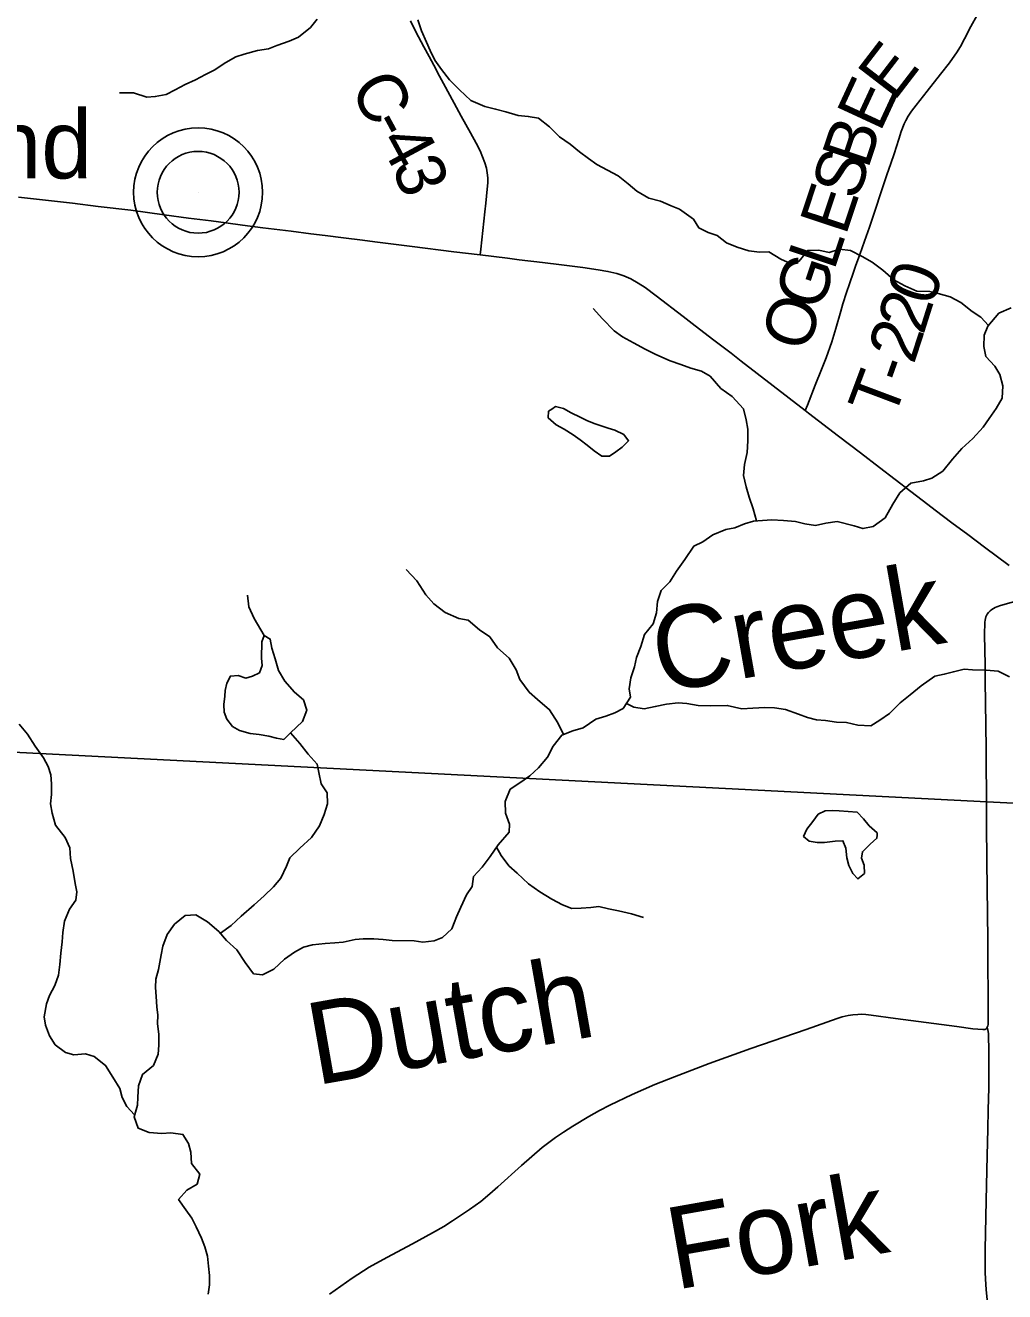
# Model space of a CAD drawing. Extents: x 1442749 to 1756758, y 235267 to 677782.
# Drawn here: x 1568709 to 1574676, y 536473 to 544190 of the extents above; entities that cross this region are included whole.
import ezdxf

# ---------------------------------------------------------------- set-up
doc = ezdxf.new("R2010")
doc.units = 0
for name, color, linetype in [('GM_X_County_Road', 7, 'Continuous'), ('GM_X_County_Road_Text', 7, 'Continuous'), ('GM_X_Major_River_Text', 7, 'Continuous'), ('GM_X_Minor_Lake', 7, 'Continuous'), ('GM_X_Minor_River', 7, 'Continuous'), ('GM_X_Minor_River_Text', 7, 'Continuous'), ('GM_X_State_Route', 7, 'Continuous'), ('GM_X_Township', 7, 'Continuous'), ('GM_X_Township_Road', 7, 'Continuous'), ('GM_X_Township_Road_Text', 7, 'Continuous'), ('GM_X_Unincorporated', 7, 'Continuous'), ('GM_X_Unincorporated_Location', 7, 'Continuous'), ('GM_X_Unincorporated_Text', 7, 'Continuous')]:
    doc.layers.add(name, color=color, linetype=linetype)

msp = doc.modelspace()

# ---------------------------------------------------------------- linework, layer by layer
at = {"layer": 'GM_X_County_Road'}
for points in [[(1571480.2, 542791.2), (1571483.9, 542826), (1571508.2, 543054.3), (1571514.2, 543106.5), (1571523.9, 543191.3), (1571526.7, 543230.9), (1571526.3, 543260.8), (1571523.6, 543290.6), (1571518.3, 543320.1), (1571509.3, 543352.1), (1571495.6, 543389.4), (1571479.6, 543425.6), (1571455.9, 543472.7), (1571421.1, 543535.8), (1571365.7, 543635.8), (1571335.5, 543690.2), (1571268.3, 543814.1), (1571233, 543880.8), (1571197.4, 543947.3), (1571169.3, 543999.3), (1571136.5, 544059.9), (1571089.2, 544149.8), (1571056.1, 544217.4)], [(1574565.9, 539401), (1574562.6, 539789.4), (1574561.3, 539916.8), (1574559.2, 540070.2), (1574557.6, 540184.8), (1574556.2, 540293), (1574553.5, 540476.5), (1574555.5, 540552.4), (1574557.3, 540565.8), (1574559.3, 540575.6), (1574561.7, 540586.3), (1574569, 540601.4), (1574576.8, 540612.2), (1574587.6, 540622.4), (1574597.8, 540630.3), (1574608.1, 540637.1), (1574617.4, 540642), (1574627.6, 540646.9), (1574651.5, 540654.2), (1574845.2, 540708.9), (1574867.7, 540715.4), (1574924.4, 540732.1)], [(1574570, 538084.6), (1574574, 538093.6), (1574575.4, 538101.5), (1574576.1, 538108.5), (1574575.4, 538292), (1574574.2, 538459.3), (1574572.8, 538619.7), (1574570.5, 538776.3), (1574567.7, 539094.1), (1574565.6, 539324.1), (1574565.9, 539401)], [(1570562.9, 536458.8), (1570700.8, 536555.8), (1570805, 536622.4), (1570910.9, 536682), (1571067.9, 536764.1), (1571191, 536832.3), (1571258.1, 536870.9), (1571312.8, 536905.6), (1571415.2, 536973.3), (1571484.5, 537022.8), (1571539.4, 537068.8), (1571588.1, 537112.9), (1571731.9, 537242.5), (1571858.4, 537352.2), (1571897.9, 537382.2), (1571939.9, 537413.5), (1571989, 537444.7), (1572044.8, 537481.3), (1572143.2, 537540.6), (1572207.8, 537576.6), (1572271.1, 537609.6), (1572407.4, 537673.9), (1572544.8, 537735.5), (1572663.7, 537783), (1572875.3, 537863.4), (1573128.5, 537954.4), (1573466.6, 538070.5), (1573655.3, 538137.6), (1573686.9, 538147.8), (1573722.4, 538155.3), (1573751.2, 538160), (1573780.7, 538162.6), (1573805, 538163.4), (1573830.2, 538161.7), (1573861.6, 538158.4), (1574010.4, 538138.8), (1574384.3, 538088.3), (1574481.6, 538075.6), (1574543.1, 538071.2), (1574554.9, 538071.7), (1574560.7, 538073.6), (1574565.6, 538077.5), (1574570, 538084.6)]]:
    msp.add_lwpolyline(points, dxfattribs=at)
at = {"layer": 'GM_X_Minor_Lake'}
for points in [[(1571916.3, 541852), (1571896.2, 541838.2), (1571895.4, 541798.1), (1571942.5, 541755.2), (1571992, 541730.1), (1572047.3, 541695), (1572088.7, 541664.1), (1572132, 541631.2), (1572175.3, 541596.3), (1572222.7, 541565.3), (1572268.7, 541564.4), (1572307.2, 541591.7)], [(1572307.2, 541591.7), (1572345.8, 541619), (1572384.6, 541658.3), (1572355.4, 541696.9), (1572300, 541724), (1572260.2, 541734.8), (1572218.5, 541749.7), (1572174.8, 541764.6), (1572131.1, 541781.5), (1572089.5, 541802.3), (1572034.1, 541829.4), (1571988.6, 541854.4), (1571938.8, 541867.4), (1571916.3, 541852)], [(1570163.9, 540472.3), (1570151.1, 540432.5), (1570149.1, 540334.4), (1570152.2, 540288.3), (1570135.3, 540244.5), (1570092.8, 540223.4), (1570052.6, 540212.1), (1570006.9, 540227.1), (1569958.8, 540224), (1569937.9, 540180.4), (1569927, 540136.5), (1569924.3, 540102.5), (1569919.2, 540050.5), (1569920.3, 540004.4), (1569937.4, 539962), (1569972.5, 539917.3), (1570014, 539892.4), (1570079.7, 539875.1), (1570133.5, 539868), (1570193.4, 539858.8), (1570239.1, 539845.9), (1570285, 539839), (1570325.8, 539878.2)], [(1570325.8, 539878.2), (1570397.2, 539946.9), (1570424.6, 540016.5), (1570403.9, 540079), (1570348.9, 540126.2), (1570290.2, 540193.4), (1570251.6, 540258.3), (1570231, 540328.8), (1570210.4, 540395.3), (1570201.5, 540449.6), (1570163.9, 540472.3)], [(1573898.7, 539255.2), (1573899.8, 539268.7), (1573850.7, 539311.7), (1573815.6, 539354.5), (1573776.4, 539395.3), (1573722.5, 539398.4), (1573668.5, 539403.5), (1573624.6, 539406.3), (1573582.5, 539403.2), (1573540.1, 539384), (1573507.2, 539338.5)], [(1573507.2, 539338.5), (1573470.2, 539291.2), (1573451.3, 539247.5), (1573484.7, 539218.8), (1573534.6, 539209.8), (1573578.6, 539210.9), (1573642.7, 539217.7), (1573690.8, 539220.8), (1573707.9, 539176.3), (1573714.7, 539116.1), (1573725.7, 539069.8), (1573750.7, 539021.2), (1573782.1, 538988.6), (1573822.7, 539021.8), (1573819.8, 539072), (1573804.6, 539114.3), (1573809.5, 539154.3), (1573856.4, 539199.4), (1573897.2, 539236.7), (1573898.7, 539255.2)]]:
    msp.add_lwpolyline(points, dxfattribs=at)
at = {"layer": 'GM_X_Minor_River'}
for points in [[(1570487, 544227.7), (1570446, 544176.4), (1570372.8, 544117.8), (1570316.2, 544092.8), (1570241.7, 544066.3), (1570191.3, 544047.2), (1570123.1, 544036.6), (1570042.6, 544014.1), (1569992.3, 543999.1), (1569931.5, 543964.2), (1569860.6, 543917.6), (1569808, 543890.6), (1569745.3, 543857.8), (1569682.7, 543828.9), (1569622.1, 543798.1), (1569567.5, 543769.1), (1569501.2, 543756.4), (1569449.1, 543751.4), (1569367.7, 543779.1), (1569283.6, 543778.8)], [(1574576.7, 542360.2), (1574530.4, 542411), (1574477.1, 542446.1), (1574408.2, 542501.6), (1574342.9, 542534.9), (1574271.3, 542556.4), (1574219.5, 542567.4), (1574141.6, 542571), (1574068.2, 542602.4), (1574001, 542639.8), (1573934.2, 542697.2), (1573869.2, 542746.6), (1573807.9, 542781.9), (1573736.6, 542817.3), (1573668.8, 542826.7), (1573606.3, 542805.9), (1573544.6, 542819.1), (1573476.6, 542818.5), (1573421.2, 542751.5), (1573370.9, 542738.4), (1573311.5, 542765.7), (1573238.4, 542809.2), (1573182.3, 542808.3), (1573116.5, 542815.6), (1573046.9, 542839), (1572981.4, 542864.3), (1572924.4, 542909.5), (1572868.7, 542928.6), (1572813.3, 542955.8), (1572780.4, 543008.5), (1572695.6, 543070.3), (1572644, 543089.3), (1572578.6, 543118.7), (1572509, 543136.1), (1572435.8, 543179.6), (1572382.8, 543224.7), (1572321.7, 543274), (1572191.1, 543342.7), (1572139.8, 543377.7), (1572084.7, 543418.9), (1572029.6, 543466), (1571964.6, 543511.4), (1571903.8, 543570.7), (1571834.9, 543624.1), (1571773.1, 543635.4), (1571711.2, 543640.6), (1571637.6, 543662.1), (1571574, 543679.4), (1571508.3, 543694.7), (1571423, 543732.4), (1571354.3, 543797.9), (1571293.6, 543857.2), (1571244.8, 543920.2), (1571204, 543977.1), (1571175.2, 544035.8), (1571154.3, 544088.3), (1571123.7, 544157), (1571101, 544223.5)], [(1570890, 538619.1), (1570943.9, 538614.1), (1571077.9, 538611.4), (1571131.7, 538602.3), (1571199.9, 538611), (1571250.4, 538632), (1571307.5, 538685), (1571336.9, 538756.5), (1571362.1, 538816.1), (1571397.7, 538891.5), (1571430.8, 538943), (1571440, 539002.9), (1571493.2, 539059.9), (1571540.5, 539125.1), (1571590, 539196.2), (1571657.6, 539273), (1571658.6, 539323), (1571634, 539389.6), (1571633.4, 539459.8), (1571662.9, 539535.3), (1571727.8, 539578.1), (1571782.6, 539617), (1571835.7, 539666.1), (1571891, 539731.1), (1571924.4, 539796.5), (1571977.7, 539863.6), (1572044.3, 539890.3), (1572108.7, 539909), (1572185.8, 539961.6), (1572246.2, 539980.4), (1572300.6, 540001.4), (1572351.1, 540026.4), (1572396.6, 540095.6), (1572387.6, 540145.9), (1572399, 540213.8), (1572420.4, 540281.5), (1572433.5, 540337.3), (1572458.9, 540404.9), (1572482.4, 540478.5), (1572533.8, 540543.6), (1572555.1, 540609.3), (1572560.6, 540679.3), (1572583.9, 540746.9), (1572635, 540798), (1572676.4, 540863.3), (1572727.8, 540934.4), (1572781.5, 541015.4), (1572838, 541042.4), (1572898.9, 541085.2), (1572977.6, 541117.7), (1573031.8, 541128.7), (1573090.3, 541151.6), (1573146.7, 541168.5), (1573200.8, 541173.4), (1573256.9, 541176.3), (1573328.8, 541172.9), (1573400.7, 541167.4), (1573458.4, 541152.3), (1573524.2, 541143), (1573586.5, 541155.8), (1573654.7, 541166.4), (1573758.2, 541140.3), (1573811.9, 541123.3), (1573874.1, 541136), (1573947.2, 541188.7), (1573994.9, 541271.9), (1574036.4, 541341.2), (1574103.6, 541399.9), (1574181.9, 541414.4), (1574232.2, 541431.4), (1574299.1, 541474.2), (1574358.6, 541547.1), (1574416, 541612.1), (1574481.2, 541672.9), (1574544.6, 541741.7), (1574581.7, 541795.1), (1574625, 541854.3), (1574660.3, 541917.7), (1574663.8, 541993.8), (1574647.2, 542062.2), (1574616.3, 542112.9), (1574561.5, 542172), (1574548.7, 542232.4), (1574550.2, 542302.5), (1574573.3, 542356.1), (1574640.9, 542436.9), (1574715.6, 542469.5)], [(1573164.1, 541170), (1573144.2, 541244.6), (1573119.7, 541315.2), (1573101, 541377.7), (1573084.4, 541446.1), (1573091.8, 541514.1), (1573107.3, 541587.9), (1573110.7, 541657.9), (1573112.2, 541730), (1573101.3, 541786.3), (1573084.7, 541852.7), (1573016.2, 541928.2), (1572947.2, 541977.6), (1572880.8, 542053.1), (1572829.4, 542082.1), (1572763.8, 542101.5), (1572702.2, 542122.7), (1572638.7, 542146), (1572551.4, 542183.8), (1572486.1, 542217.1), (1572414.8, 542254.6), (1572347.6, 542292), (1572296.4, 542329), (1572225.9, 542402.5), (1572169.1, 542463.8)], [(1571987.7, 539867.6), (1571953.3, 539940.2), (1571902.9, 540019.3), (1571830.2, 540080.8), (1571779.1, 540125.9), (1571722.7, 540203.1), (1571699.9, 540261.7), (1571657.3, 540334.6), (1571586.6, 540396.1), (1571540, 540463.1), (1571476.8, 540506.4), (1571408.1, 540565.9), (1571350.2, 540575), (1571267, 540612.8), (1571198, 540664.2), (1571149.2, 540719.2), (1571094.9, 540804.4), (1571030.3, 540873.8)], [(1569897.8, 538656.9), (1569963.6, 538703.6), (1570024.8, 538760.5), (1570104.3, 538831), (1570165.4, 538885.9), (1570220.5, 538940.9), (1570265.6, 538992), (1570301.1, 539065.5), (1570320.2, 539117.2), (1570381.4, 539176), (1570452.7, 539240.7), (1570502.2, 539311.9), (1570529.6, 539381.4), (1570550.9, 539445.1), (1570548.3, 539513.3), (1570511.4, 539568.1), (1570496.8, 539636.5), (1570487.9, 539688.7), (1570433.1, 539747.9), (1570382.4, 539813), (1570325.8, 539878.2), (1570397.2, 539946.9), (1570424.6, 540016.5), (1570403.9, 540079), (1570348.9, 540126.2), (1570290.2, 540193.4), (1570251.6, 540258.3), (1570231, 540328.8), (1570210.4, 540395.3), (1570201.5, 540449.6), (1570163.9, 540472.3), (1570104, 540575.7), (1570071.5, 540646.4), (1570062.9, 540716.7)], [(1572371.5, 540057.5), (1572417.3, 540035.2), (1572479.1, 540025.9), (1572547.4, 540038.6), (1572615.7, 540053.3), (1572685.9, 540061.9), (1572739.8, 540056.8), (1572809.6, 540045.4), (1572883.6, 540043.9), (1572985.6, 540045.9), (1573075.2, 540024.1), (1573141.3, 540028.8), (1573215.4, 540033.4), (1573273.3, 540030.2), (1573341.2, 540020.9), (1573420.6, 539993.3), (1573474.2, 539972.2), (1573529.9, 539957), (1573583.8, 539954), (1573651.6, 539944.6), (1573711.6, 539941.4), (1573781.3, 539926), (1573861.2, 539920.4), (1573915.9, 539955.4), (1573974.8, 539996.3), (1574040.1, 540061.1), (1574101.1, 540110), (1574168.2, 540164.8), (1574251.5, 540223.2), (1574307.7, 540236.1), (1574364, 540251), (1574428.4, 540265.8), (1574480.3, 540262.7), (1574562.3, 540261.1), (1574636.1, 540253.7), (1574705.5, 540220.2)], [(1569375.4, 537551.6), (1569326.9, 537602.5), (1569300, 537657.1), (1569285.2, 537711.4), (1569242.6, 537780.4), (1569198, 537851.4), (1569129.1, 537906.8), (1569075.4, 537921.9), (1569005.3, 537917.3), (1568953.6, 537930.3), (1568890.6, 537977.7), (1568855.7, 538032.4), (1568833, 538097), (1568824, 538147.2), (1568837.7, 538227.1), (1568856.7, 538278.8), (1568889.9, 538338.2), (1568911.3, 538401.9), (1568920.6, 538467.8), (1568926, 538535.8), (1568933.4, 538605.8), (1568938.6, 538661.8), (1568948, 538731.7), (1568979.5, 538803.2), (1569016.6, 538858.5), (1569023.7, 538910.5), (1569012.7, 538960.8), (1569000.3, 539035.1), (1568983.9, 539113.6), (1568981.2, 539177.7), (1568952.5, 539240.4), (1568894, 539315.7), (1568873.5, 539388.2), (1568862.7, 539446.5), (1568869.8, 539502.4), (1568869.2, 539568.5), (1568864.3, 539622.7), (1568849.3, 539673.1), (1568820.4, 539725.7), (1568769.9, 539796.9), (1568723.3, 539869.9), (1568672.6, 539931)], [(1571580.5, 539182.5), (1571608.7, 539131.7), (1571655.4, 539068.7), (1571706.5, 539023.6), (1571775.1, 538958.2), (1571844.1, 538908.7), (1571917.2, 538865.2), (1571982.5, 538829.9), (1572038.1, 538808.8), (1572096.1, 538809.6), (1572154.2, 538814.5), (1572204.4, 538819.5), (1572262.1, 538806.3), (1572323.8, 538793.1), (1572401.5, 538775.5), (1572475.1, 538754)], [(1569823.5, 536456.9), (1569830.7, 536514.8), (1569831.9, 536570.9), (1569825.1, 536629.1), (1569818.3, 536689.3), (1569803.4, 536745.7), (1569782.5, 536798.2), (1569750, 536869), (1569723, 536921.6), (1569688.1, 536972.3), (1569643.4, 537035.3), (1569692.5, 537092.4), (1569757.3, 537129.2), (1569772.5, 537189), (1569721.9, 537254.1), (1569717.3, 537322.3), (1569704.4, 537376.7), (1569669.5, 537431.4), (1569595.7, 537440.9), (1569541.6, 537438), (1569463.7, 537443.5), (1569396.2, 537468.9), (1569371.7, 537539.5), (1569393.1, 537609.2), (1569394.1, 537659.2), (1569399.5, 537727.2), (1569422.9, 537796.9), (1569490.1, 537851.6), (1569519.5, 537921.2), (1569522.6, 537975.2), (1569522, 538041.3), (1569515.3, 538107.5), (1569516.4, 538157.6), (1569511.4, 538209.8), (1569506.7, 538271.9), (1569501.8, 538326.1), (1569504.9, 538378.1), (1569520.1, 538435.9), (1569537.9, 538525.7), (1569547, 538577.6), (1569574.4, 538649.2), (1569617.8, 538712.4), (1569682.8, 538765.2), (1569749, 538769.9), (1569820.1, 538726.4), (1569888.9, 538667), (1569935.8, 538614), (1569998.6, 538556.7), (1570049, 538479.5), (1570099.6, 538410.4), (1570153.5, 538403.4), (1570224.2, 538438), (1570287.5, 538498.9), (1570348.4, 538541.7), (1570405, 538572.7), (1570459.3, 538587.6), (1570535.5, 538594.1), (1570595.6, 538598.9), (1570645.7, 538603.9), (1570718, 538618.5), (1570768.1, 538623.6), (1570832.1, 538624.3), (1570890, 538619.1)]]:
    msp.add_lwpolyline(points, dxfattribs=at)
at = {"layer": 'GM_X_State_Route'}
msp.add_lwpolyline([(1568668.5, 543143.6), (1568997.8, 543106), (1569154, 543086.4), (1569352.9, 543063.1), (1569554.5, 543035.9), (1569704, 543016), (1569840.8, 542998.7), (1569931.7, 542986), (1570032.4, 542972.1), (1570156, 542957.1), (1570328.3, 542935), (1570448.8, 542920.4), (1570536.7, 542909.3), (1570647.2, 542894.7), (1570764.3, 542880.5), (1570839.2, 542871.2), (1571067.1, 542842.2), (1571321, 542810.5), (1571480.2, 542791.2), (1571646.6, 542771), (1571675.9, 542767.4), (1571718.2, 542761.4), (1571770.3, 542755.6), (1571825.6, 542748.2), (1571942.7, 542734.8), (1572105.4, 542713.7), (1572199.6, 542699.9), (1572258.4, 542690.7), (1572313.5, 542676.9), (1572354.9, 542663.8), (1572398.3, 542644.6), (1572443.7, 542619.7), (1572485.8, 542592.2), (1572552.6, 542542.6), (1572717.5, 542415.1), (1572790.6, 542359.5), (1572904.7, 542271.4), (1573008.8, 542191.5), (1573071.3, 542143.6), (1573461, 541842.8), (1573481.5, 541827), (1573663.7, 541687.2), (1573796.8, 541585.9), (1573914, 541496.2), (1574103.5, 541349.7), (1574207.5, 541269.8), (1574251.8, 541235.9), (1574353.9, 541159.1), (1574451.1, 541086.8), (1574553.3, 541010.5), (1574702.4, 540898.8)], dxfattribs=at)
at = {"layer": 'GM_X_Township'}
for points in [[(1567480, 573617.6), (1572928.5, 573040.3), (1578512.8, 572448.5), (1578437.8, 571716.9), (1577744.9, 564960.2), (1577349.2, 561102), (1576813.8, 555881.3), (1576704.1, 554811.5), (1576385.5, 550843.6), (1576369, 550638.4), (1576189.1, 548397.4), (1576128.9, 547648.1), (1575922.4, 544864.2), (1575630.5, 540930.9), (1575571.3, 540238.8), (1575500.4, 539411), (1574567.9, 539458.5), (1566007.1, 539894.4)], [(1566007.1, 539894.4), (1574567.9, 539458.5), (1575500.4, 539411), (1576764.1, 539348.5), (1576884.4, 539342.6), (1576886.4, 539252.1), (1577095.4, 529536.7), (1577246.7, 522507.3), (1577335.5, 518378.1), (1577466, 512312.2), (1577284.9, 512328.8), (1572224.6, 512792.5), (1572116.5, 513572.1), (1570495.5, 513586.9), (1570073.6, 513943.9), (1565959.1, 517425.5)]]:
    msp.add_lwpolyline(points, dxfattribs=at)
at = {"layer": 'GM_X_Township_Road'}
for points in [[(1573461, 541842.8), (1573473.8, 541874.8), (1573522.3, 541996.9), (1573560.4, 542093.2), (1573587.7, 542163.3), (1573622.1, 542260.8), (1573647.5, 542342), (1573677.7, 542449.3), (1573690.9, 542492), (1573713, 542562.4), (1573730.9, 542614.3), (1573755.1, 542685.1), (1573768, 542721.7), (1573794.4, 542793.7), (1573821.8, 542873.9), (1573851.7, 542960.2), (1573958.1, 543279.6), (1573982.1, 543347.4), (1574002.8, 543406.1), (1574030.5, 543497), (1574046.2, 543543.8), (1574064.4, 543589.8), (1574074, 543610.9), (1574088.3, 543637.1), (1574108, 543667.7), (1574135.8, 543704.6), (1574202.9, 543789.6), (1574284.9, 543892.1), (1574339.6, 543961.4), (1574359, 543987.8), (1574382.6, 544022.9), (1574407.3, 544061.1), (1574431.2, 544107.4), (1574470.8, 544182.5), (1574508.2, 544251.7)], [(1574578.3, 536340.1), (1574563.9, 536486.9), (1574559.8, 536550.3), (1574557.8, 536591.6), (1574556.3, 536730), (1574562.4, 537028), (1574569.4, 537302.9), (1574573, 537463.4), (1574575.5, 537581.3), (1574578.5, 537715.8), (1574579.7, 537863.2), (1574578.8, 537948.4), (1574577.3, 538027.8), (1574576.9, 538044.7), (1574575.3, 538059.1), (1574570, 538084.6)]]:
    msp.add_lwpolyline(points, dxfattribs=at)
at = {"layer": 'GM_X_Unincorporated'}
for radius in [392.8, 249]:
    msp.add_circle((1569762.2, 543172.6), radius, dxfattribs=at)
at = {"layer": 'GM_X_Unincorporated_Location'}
msp.add_line((1569762.2, 543172.6), (1569762.2, 543172.6), dxfattribs=at)

# ---------------------------------------------------------------- texts
at = {"layer": 'GM_X_County_Road_Text'}
for s, rotation, p in [('C', 298.43121, (1570682, 543810.2)), ('-', 298.41205, (1570799.3, 543593.5)), ('4', 298.3598, (1570857.9, 543485.2)), ('3', 289.89819, (1570940.9, 543333.3))]:
    msp.add_text(s, height=300, rotation=rotation, dxfattribs=at).set_placement(p)
at = {"layer": 'GM_X_Major_River_Text'}
msp.add_text('Fork', height=499.98, rotation=9.99954, dxfattribs=at).set_placement((1572669.3, 536483.5))
at = {"layer": 'GM_X_Minor_River_Text'}
for s, height, rotation, p in [('Creek', 499.98, 9.99908, (1572575.9, 540119.6)), ('Dutch', 499.99, 9.99893, (1570479.5, 537730))]:
    msp.add_text(s, height=height, rotation=rotation, dxfattribs=at).set_placement(p)
at = {"layer": 'GM_X_Township_Road_Text'}
for s, rotation, p in [('E', 52.47008, (1574002, 543721.9)), ('E', 65.15631, (1573916.8, 543533.3)), ('B', 71.4626, (1573841.7, 543307.8)), ('S', 71.61988, (1573777.9, 543115.9)), ('E', 71.61722, (1573707.2, 542902.9)), ('L', 71.61925, (1573636.4, 542690)), ('G', 71.61803, (1573553.1, 542439.4)), ('0', 71.17752, (1574235, 542471.9)), ('O', 71.61803, (1573469.9, 542188.9)), ('2', 72.46983, (1574179.9, 542297.4)), ('2', 71.9823, (1574121.9, 542119)), ('-', 70.46797, (1574078, 541994.7)), ('T', 69.42589, (1573997.1, 541779.1))]:
    msp.add_text(s, height=300, rotation=rotation, dxfattribs=at).set_placement(p)
at = {"layer": 'GM_X_Unincorporated_Text'}
msp.add_text('Oakland', height=417, rotation=0.00001, dxfattribs=at).set_placement((1567039.6, 543257.3))

doc.saveas('drawing.dxf')
